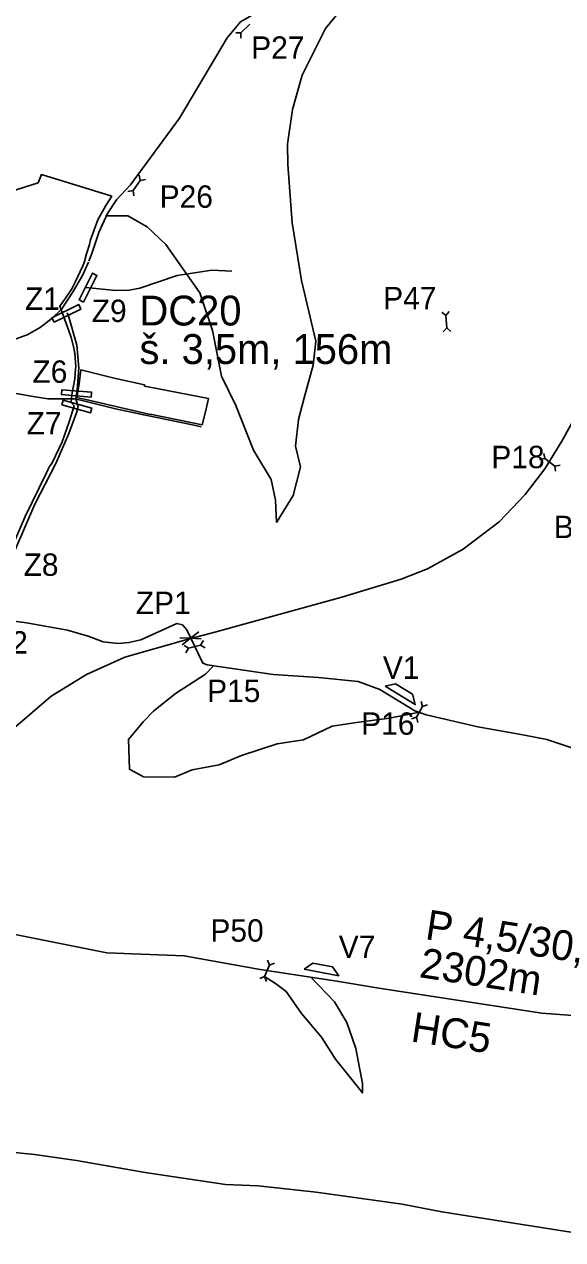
# Model space of a CAD drawing. Extents: x -638669 to -632369, y -1091026 to -1088056.
# Drawn here: x -635193 to -634652, y -1089928 to -1088706 of the extents above; entities that cross this region are included whole.
import ezdxf

# ---------------------------------------------------------------- set-up
doc = ezdxf.new("R2010")
doc.units = 0
for name, color, linetype in [('01_DOPRAVA', 7, 'Continuous'), ('01_DOPRAVA_MIMO_OBVOD', 7, 'Continuous'), ('01_OBVOD PÚ', 7, 'Continuous'), ('01_SPRÁV_HRANICE_STAV', 7, 'Continuous'), ('03_PC_NÁVRH', 7, 'Continuous'), ('03_PC_OBJEKTY_NÁVRH', 7, 'Continuous'), ('03_PC_OBJEKTY_STAV', 7, 'Continuous'), ('03_PC_POPIS_NÁVRH', 7, 'Continuous'), ('03_PC_POPIS_STAV', 7, 'Continuous'), ('03_PC_STAV', 7, 'Continuous'), ('05_VHO_ROZVODÍ', 7, 'Continuous')]:
    doc.layers.add(name, color=color, linetype=linetype)

msp = doc.modelspace()

# ---------------------------------------------------------------- linework, layer by layer
at = {"layer": '01_DOPRAVA'}
for points in [[(-635156, -1088993.1), (-635144.4, -1088975.7), (-635134.5, -1088958.7), (-635128.6, -1088945.2)], [(-635204.2, -1089414.2), (-635166.1, -1089381.4), (-635130.4, -1089359.8), (-635092, -1089342.3), (-635030.6, -1089324.9), (-635001.6, -1089317.2), (-634873.9, -1089282.1), (-634814.2, -1089263.8), (-634787.8, -1089253.6), (-634751.7, -1089233.7), (-634715.8, -1089206.3), (-634689.5, -1089178.7), (-634669.8, -1089152.9), (-634652.6, -1089125.3), (-634631.7, -1089086.9)], [(-635142.9, -1089082.8), (-635145.6, -1089082.8)], [(-635142.9, -1089082.8), (-635136, -1089084), (-635101.3, -1089092.6), (-635072.9, -1089098.9), (-635023.8, -1089108.9), (-635015.1, -1089110.7)]]:
    msp.add_lwpolyline(points, dxfattribs=at)
at = {"layer": '01_DOPRAVA_MIMO_OBVOD'}
for points in [[(-635274.1, -1089051.8), (-635258.3, -1089031.2), (-635251.5, -1089027.6), (-635240.7, -1089025.6), (-635221.2, -1089026.3), (-635205.7, -1089024.1), (-635190.1, -1089018.4), (-635176.9, -1089011), (-635164.8, -1089001.8), (-635156.1, -1088993.2), (-635156, -1088993.1)], [(-635145.6, -1089082.8), (-635169.2, -1089082.7), (-635184, -1089080.5), (-635243, -1089069.9), (-635260.6, -1089065.1), (-635273.2, -1089063.4)]]:
    msp.add_lwpolyline(points, dxfattribs=at)
at = {"layer": '01_OBVOD PÚ'}
for points in [[(-635206.5, -1088874.4), (-635179.1, -1088865.6), (-635175.8, -1088857.4), (-635105.1, -1088879.1), (-635110.9, -1088888.4), (-635119.1, -1088902.9), (-635126.3, -1088922.9), (-635127.6, -1088927.6), (-635130.4, -1088937.1), (-635132.6, -1088944.6), (-635134.1, -1088948.9), (-635141.8, -1088965.5), (-635145.1, -1088972), (-635148, -1088976.1), (-635154.7, -1088985.9), (-635157.3, -1088989.7), (-635153.6, -1088999.6), (-635148.4, -1089013.2), (-635145.8, -1089021.2), (-635143.2, -1089031.3), (-635142.1, -1089037.1), (-635141.3, -1089050.4), (-635141.4, -1089052.2), (-635142.3, -1089062.6), (-635144.7, -1089076.8), (-635145.5, -1089081.9), (-635145.7, -1089086.4), (-635142.8, -1089089.6), (-635147.8, -1089105.7), (-635154.8, -1089126), (-635165, -1089147), (-635167.8, -1089150.6), (-635169.3, -1089154.1), (-635170.9, -1089157.9), (-635192.2, -1089201), (-635204.6, -1089229.7)], [(-634594.6, -1089927.7), (-634773.4, -1089899.8), (-634813.2, -1089892.1), (-634899.6, -1089879.9), (-634958, -1089873.7), (-634990.6, -1089872.2), (-635071.4, -1089860.1), (-635140.6, -1089848.1), (-635182.8, -1089842), (-635209.2, -1089839.5)]]:
    msp.add_lwpolyline(points, dxfattribs=at)
msp.add_lwpolyline([(-635068.3, -1089070.6), (-635007.8, -1089082.4), (-635011, -1089095.6), (-635014.3, -1089108.9), (-635064.9, -1089098.6), (-635067.8, -1089098), (-635131.2, -1089083.4), (-635140.1, -1089081.2), (-635137.8, -1089067.6), (-635136.3, -1089053.7), (-635102.8, -1089061.8), (-635072, -1089068.8), (-635072, -1089069.9)], close=True, dxfattribs=at)
at = {"layer": '01_SPRÁV_HRANICE_STAV'}
msp.add_lwpolyline([(-634594.6, -1089927.7), (-634773.4, -1089899.8), (-634813.2, -1089892.1), (-634899.6, -1089879.9), (-634958, -1089873.7), (-634990.6, -1089872.2), (-635071.4, -1089860.1), (-635140.6, -1089848.1), (-635182.8, -1089842), (-635209.2, -1089839.5)], dxfattribs=at)
at = {"layer": '03_PC_NÁVRH'}
for points in [[(-635128, -1088944.3), (-635125, -1088936.7), (-635118, -1088915.6), (-635109.5, -1088896.3), (-635100.2, -1088882.8), (-635086.3, -1088867.5), (-635036.9, -1088800.7), (-634989.2, -1088720.1), (-634975.5, -1088704), (-634949.6, -1088688.7), (-634916.5, -1088678.7), (-634874, -1088670.8), (-634834, -1088666.3), (-634787.1, -1088670.5), (-634730.9, -1088679.4), (-634676.9, -1088680.4), (-634604.9, -1088690.7)], [(-635149.9, -1088996.4), (-635148.6, -1088999.3), (-635140.2, -1089028.8), (-635138.2, -1089051.4), (-635139.7, -1089074), (-635141.3, -1089083.2), (-635138.8, -1089090.4), (-635140.5, -1089096.7), (-635148.1, -1089117.6), (-635161.2, -1089147.6), (-635182.3, -1089188.6), (-635202.1, -1089234.4)], [(-635215.4, -1089304.3), (-635190.9, -1089307.7), (-635149.4, -1089315.1), (-635128.9, -1089321.1), (-635113.6, -1089326.9), (-635098.6, -1089328.6), (-635087.8, -1089327.6), (-635076, -1089324.8), (-635039.8, -1089308.6), (-635034.1, -1089309.9), (-635029.6, -1089314.8), (-635013.5, -1089348.4), (-635009.1, -1089350.1), (-634942.7, -1089359.8), (-634897.2, -1089362.7), (-634857.4, -1089366.9), (-634835.5, -1089374.8), (-634800.5, -1089396.1), (-634789.1, -1089400.4), (-634737.2, -1089412.4), (-634691.9, -1089420.3), (-634667.7, -1089425.1), (-634604.7, -1089446)], [(-635275.5, -1089608.7), (-635251.2, -1089611.3), (-635109.9, -1089639.3), (-635032.2, -1089642.4), (-634956, -1089656.1), (-634878.9, -1089667.8), (-634836.7, -1089674.9), (-634672.6, -1089700.1), (-634583.6, -1089706.6)]]:
    msp.add_lwpolyline(points, dxfattribs=at)
at = {"layer": '03_PC_OBJEKTY_NÁVRH'}
for points in [[(-635030.5, -1089337.9), (-635027.8, -1089333.3), (-635032.4, -1089330.6)], [(-635015.7, -1089330.2), (-635027.8, -1089333.3)], [(-635011.1, -1089333), (-635015.7, -1089330.2), (-635013, -1089325.7)], [(-634946.5, -1089651.7), (-634951.4, -1089663.3)], [(-634941.6, -1089649.7), (-634946.5, -1089651.7), (-634948.5, -1089646.8)], [(-634949.4, -1089668.2), (-634951.4, -1089663.3), (-634956.3, -1089665.3)]]:
    msp.add_lwpolyline(points, dxfattribs=at)
for points in [[(-634830.1, -1089371.6), (-634819.8, -1089369.1), (-634802.7, -1089379.5), (-634800, -1089389.9)], [(-634911.5, -1089655.9), (-634902.8, -1089649.9), (-634883.1, -1089653.6), (-634876.9, -1089662.4)]]:
    msp.add_lwpolyline(points, close=True, dxfattribs=at)
at = {"layer": '03_PC_OBJEKTY_STAV'}
for points in [[(-634975.2, -1088715), (-634966.4, -1088706.2)], [(-634980.5, -1088715), (-634975.2, -1088715), (-634975.2, -1088720.3)], [(-635077.4, -1088858.1), (-635076.5, -1088863.3), (-635071.3, -1088862.4)], [(-635083.7, -1088873.5), (-635076.5, -1088863.3)], [(-635088.9, -1088874.4), (-635083.7, -1088873.5), (-635082.8, -1088878.8)], [(-635133.5, -1088985.4), (-635137.9, -1088983.1), (-635124.3, -1088956.4), (-635119.9, -1088958.7), (-635133.5, -1088985.4)], [(-635163, -1089005.7), (-635165.2, -1089001.2), (-635138.3, -1088988), (-635136.1, -1088992.5), (-635163, -1089005.7)], [(-634773.2, -1088995.6), (-634769.2, -1088999.1), (-634765.8, -1088995.1)], [(-634768.4, -1089011.5), (-634769.2, -1088999.1)], [(-634771.8, -1089015.5), (-634768.4, -1089011.5), (-634764.3, -1089015)], [(-635155.6, -1089078.5), (-635155.2, -1089073.5), (-635125.3, -1089075.9), (-635125.7, -1089080.9), (-635155.6, -1089078.5)], [(-635155.4, -1089088.7), (-635154, -1089083.9), (-635125.2, -1089092), (-635126.5, -1089096.8), (-635155.4, -1089088.7)], [(-634670.6, -1089137.6), (-634669.8, -1089142.8), (-634675, -1089143.7)], [(-634659.7, -1089150.2), (-634669.8, -1089142.8)], [(-634654.4, -1089149.3), (-634659.7, -1089150.2), (-634658.9, -1089155.4)], [(-635036.6, -1089322.8), (-635026, -1089323.3), (-635034.4, -1089329.9)], [(-635017.6, -1089316.7), (-635026, -1089323.3), (-635015.3, -1089323.8)], [(-634798.7, -1089402.7), (-634792.7, -1089391.8)], [(-634787.6, -1089390.3), (-634792.7, -1089391.8), (-634794.1, -1089386.7)], [(-634797.3, -1089407.8), (-634798.7, -1089402.7), (-634803.8, -1089404.2)]]:
    msp.add_lwpolyline(points, dxfattribs=at)
at = {"layer": '03_PC_STAV'}
msp.add_lwpolyline([(-635131, -1088970.9), (-635100.9, -1088973.8), (-635087.7, -1088973.6), (-635077, -1088971.6), (-635039.2, -1088958.6), (-635004.5, -1088953.3), (-634984.5, -1088954.4)], dxfattribs=at)
at = {"layer": '05_VHO_ROZVODÍ'}
for points in [[(-634856.1, -1088668.8), (-634890.3, -1088710.5), (-634913.8, -1088757.6), (-634923.3, -1088791.8), (-634928.5, -1088826.8), (-634928.2, -1088847.3), (-634923.7, -1088905.8), (-634914.4, -1088963.8), (-634900, -1089024.8)], [(-635111.2, -1088898.8), (-635088.8, -1088898.8), (-635069.5, -1088909.9), (-635050.6, -1088927.7), (-635031.6, -1088954.7), (-635016.6, -1088976.1), (-635003.8, -1089013.9), (-634994.7, -1089060), (-634980.3, -1089089.4), (-634962.5, -1089134.2), (-634944.8, -1089163.8)], [(-634900, -1089024.8), (-634902.6, -1089048.8), (-634911.5, -1089081.7), (-634917.3, -1089103.6), (-634920.2, -1089130.2), (-634915.3, -1089151.2), (-634922.6, -1089180), (-634939.3, -1089207.1)], [(-634944.8, -1089163.8), (-634940.5, -1089184.4), (-634939.3, -1089207.1)], [(-635002.9, -1089351), (-635010.9, -1089359.3), (-635028, -1089370.4), (-635041.1, -1089378.9), (-635063, -1089396.7), (-635073.5, -1089407.4), (-635088.3, -1089425.1)], [(-634797.4, -1089397.9), (-634825.9, -1089403.5), (-634858.9, -1089408.1), (-634883.4, -1089411.5), (-634912.2, -1089425.4), (-634938.8, -1089429.5), (-634974.6, -1089441.1), (-634997.1, -1089450.5), (-635024.2, -1089455.5), (-635042, -1089463), (-635073.3, -1089462.4), (-635087.3, -1089454.9), (-635088.3, -1089425.1)], [(-634951.4, -1089663.3), (-634940.4, -1089670.3), (-634929.7, -1089678.4), (-634914.3, -1089700.5), (-634894.2, -1089724), (-634880, -1089746.2), (-634865.1, -1089765.1), (-634853.1, -1089780.2), (-634852.9, -1089770.8)], [(-634905.1, -1089663.8), (-634881.2, -1089688.5), (-634868.9, -1089709.5), (-634859.8, -1089735.5), (-634852.9, -1089770.8)]]:
    msp.add_lwpolyline(points, dxfattribs=at)

# ---------------------------------------------------------------- texts
at = {"layer": '03_PC_OBJEKTY_NÁVRH'}
for s, p in [('V1', (-634832.5, -1089364.1)), ('P15', (-635009.2, -1089387.4)), ('P50', (-635005.9, -1089628.2)), ('V7', (-634876.9, -1089644.6))]:
    msp.add_text(s, height=22.5, dxfattribs=at).set_placement(p)
at = {"layer": '03_PC_OBJEKTY_STAV'}
for s, p in [('P27', (-634964.9, -1088741)), ('P26', (-635056.9, -1088890.7)), ('Z1', (-635192.3, -1088993.3)), ('P47', (-634832.2, -1088992.7)), ('Z9', (-635125.2, -1089005.5)), ('Z6', (-635184.8, -1089066.6)), ('Z7', (-635190.7, -1089118.5)), ('P18', (-634723.5, -1089152.4)), ('B3', (-634660.7, -1089222.6)), ('Z8', (-635193.7, -1089260.6)), ('ZP1', (-635080.9, -1089299)), ('Z2', (-635224.6, -1089338.7)), ('P16', (-634854.3, -1089420.3))]:
    msp.add_text(s, height=22.5, dxfattribs=at).set_placement(p)
at = {"layer": '03_PC_POPIS_NÁVRH'}
for s, p in [('P 4,5/30,', (-634790.9, -1089625.5)), ('2302m', (-634796.8, -1089663.8)), ('HC5', (-634805.4, -1089728.3))]:
    msp.add_text(s, height=30, rotation=351.2499, dxfattribs=at).set_placement(p)
at = {"layer": '03_PC_POPIS_STAV'}
for s, p in [('DC20', (-635077.2, -1089009)), ('š. 3,5m, 156m', (-635077.2, -1089047.7))]:
    msp.add_text(s, height=30, dxfattribs=at).set_placement(p)

doc.saveas('drawing.dxf')
